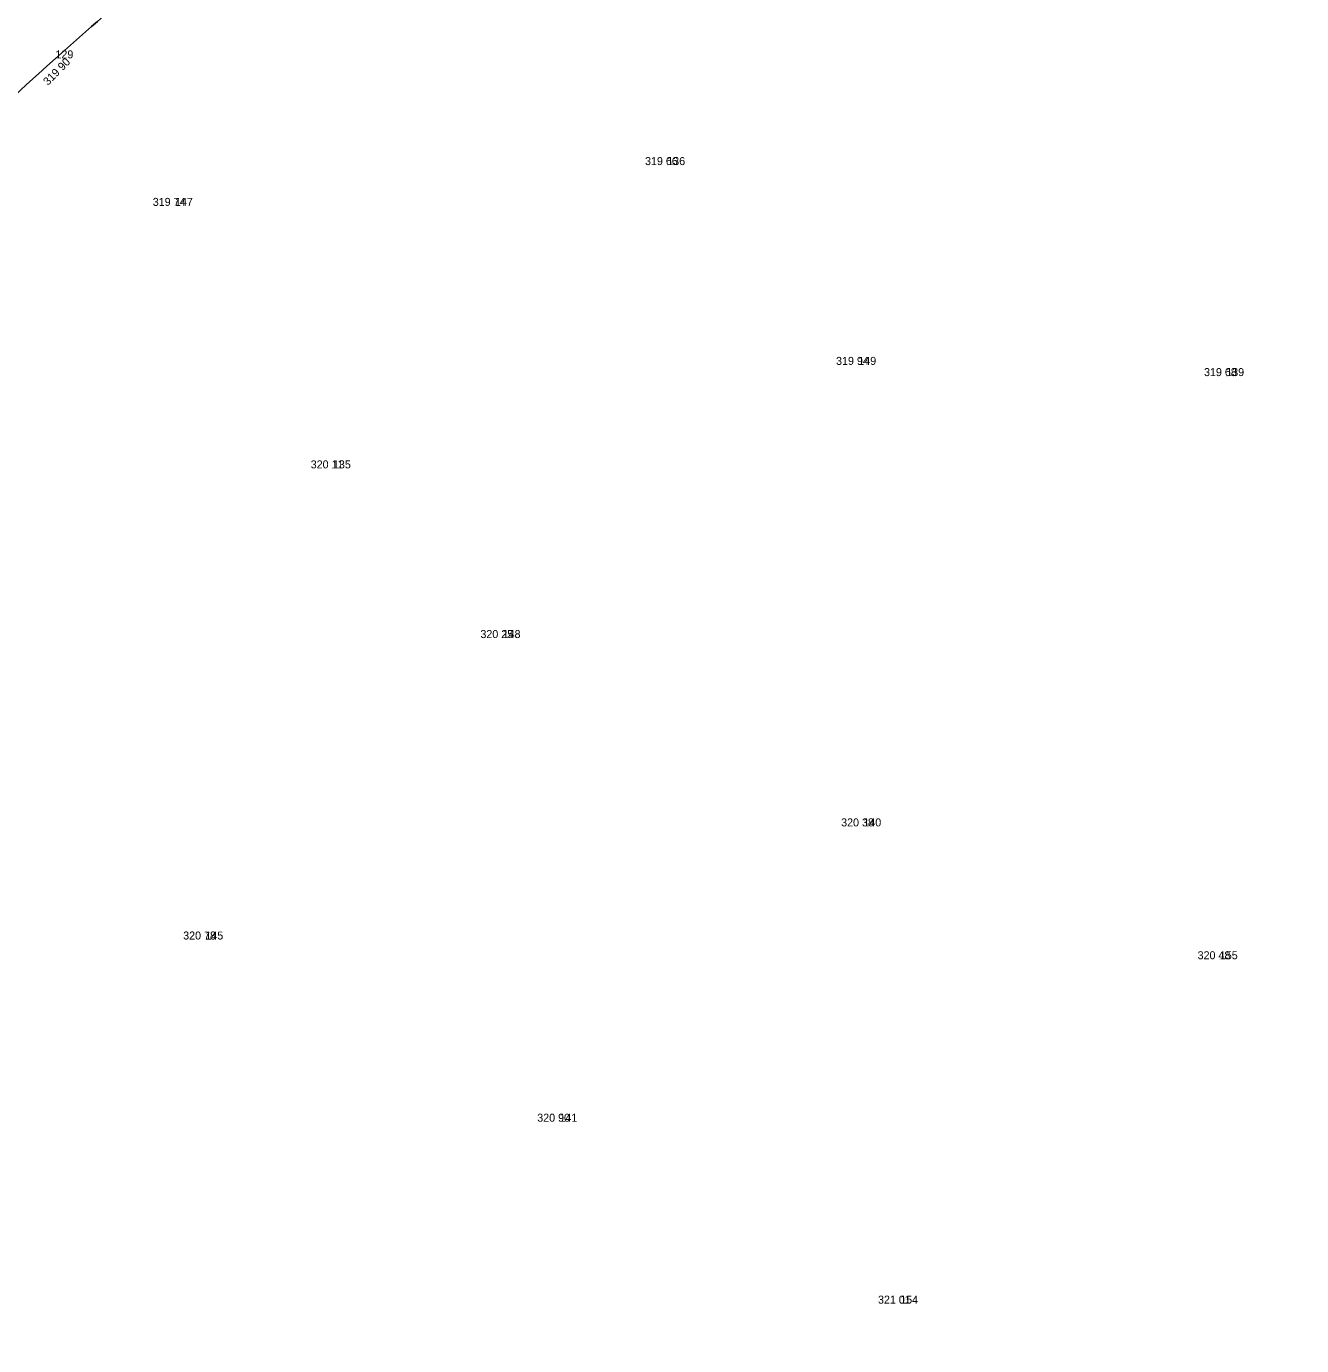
# Model space of a CAD drawing. Extents: x -742884 to -742543, y -1054677 to -1054433.
# Drawn here: x -742753.9 to -742706.11, y -1054570.07 to -1054520.62 of the extents above; entities that cross this region are included whole.
import ezdxf

# ---------------------------------------------------------------- set-up
doc = ezdxf.new("R2010")
doc.units = 0
for name, color, linetype in [('Vrstva 1', 7, 'Continuous'), ('Vrstva 11', 7, 'Continuous'), ('Vrstva 2', 7, 'Continuous'), ('Vrstva 3', 7, 'Continuous'), ('Vrstva 4', 7, 'Continuous')]:
    doc.layers.add(name, color=color, linetype=linetype)

msp = doc.modelspace()

# ---------------------------------------------------------------- linework, layer by layer
at = {"layer": 'Vrstva 1'}
for p, q in [((-742752.81, -1054521.82), (-742752.81, -1054521.82)), ((-742729.88, -1054525.82), (-742729.88, -1054525.82)), ((-742748.33, -1054527.35), (-742748.33, -1054527.35)), ((-742722.72, -1054533.31), (-742722.72, -1054533.31)), ((-742708.93, -1054533.73), (-742708.93, -1054533.73)), ((-742742.41, -1054537.19), (-742742.41, -1054537.19)), ((-742736.05, -1054543.55), (-742736.05, -1054543.55)), ((-742722.53, -1054550.61), (-742722.53, -1054550.61)), ((-742747.19, -1054554.85), (-742747.19, -1054554.85)), ((-742709.17, -1054555.59), (-742709.17, -1054555.59)), ((-742733.92, -1054561.68), (-742733.92, -1054561.68)), ((-742721.15, -1054568.5), (-742721.15, -1054568.5))]:
    msp.add_line(p, q, dxfattribs=at)
at = {"layer": 'Vrstva 11'}
for points in [[(-742777.63, -1054542.12), (-742764.61, -1054526.83), (-742751.7, -1054511.56), (-742738.47, -1054495.82), (-742727.02, -1054482.18), (-742726.38, -1054482.19), (-742725.15, -1054482.94)], [(-742776.7, -1054542.68), (-742764.01, -1054527.79), (-742751.11, -1054512.75), (-742737.61, -1054496.47), (-742726.42, -1054483.98), (-742725.9, -1054484.03), (-742714, -1054491.86), (-742704.819, -1054497.481), (-742700.94, -1054500.269), (-742696.44, -1054503.39), (-742688.83, -1054509.5), (-742682.54, -1054514.17), (-742675.15, -1054519.77), (-742673.01, -1054522.11), (-742671.05, -1054524.7)], [(-742641.45, -1054542), (-742646.08, -1054542.32), (-742650.28, -1054545.1), (-742653.63, -1054549.14), (-742658.66, -1054557.13), (-742664.13, -1054565.84), (-742667.81, -1054569.62), (-742669.76, -1054570.07), (-742674.4, -1054567.88), (-742684.66, -1054562.03), (-742693.02, -1054556.88), (-742694.43, -1054554.37), (-742693.99, -1054552.67), (-742684.52, -1054539.64), (-742677.51, -1054529.95), (-742676.26, -1054526.54), (-742677.27, -1054522.39), (-742681.19, -1054517.29), (-742689.28, -1054510.73), (-742697.86, -1054505.14), (-742704.02, -1054502.75), (-742713.11, -1054501.07), (-742723.98, -1054503.51), (-742736.77, -1054510.1), (-742745.39, -1054515.75), (-742752.81, -1054521.82), (-742762.72, -1054531.38), (-742770.54, -1054539.36), (-742775.54, -1054544.64)]]:
    msp.add_spline(points, degree=3, dxfattribs=at)
at = {"layer": 'Vrstva 4'}
for points in [[(-742783.23, -1054536.93), (-742770.7, -1054522.44), (-742757.28, -1054506.67), (-742744.15, -1054491.3), (-742731.95, -1054477.03), (-742724.73, -1054468.59)], [(-742718.8, -1054478.84), (-742709.4, -1054484.88), (-742695.99, -1054493.43), (-742680.4, -1054503.55), (-742661.01, -1054516), (-742635.78, -1054532.31)], [(-742778.49, -1054541.37), (-742765.63, -1054526.43), (-742752.39, -1054510.77), (-742739.19, -1054495.37), (-742727.3, -1054481.14)]]:
    msp.add_spline(points, degree=3, dxfattribs=at)

# ---------------------------------------------------------------- texts
at = {"layer": 'Vrstva 2'}
for s, p in [('129', (-742752.81, -1054521.82)), ('136', (-742729.88, -1054525.82)), ('147', (-742748.33, -1054527.35)), ('149', (-742722.72, -1054533.31)), ('139', (-742708.93, -1054533.73)), ('135', (-742742.41, -1054537.19)), ('148', (-742736.05, -1054543.55)), ('140', (-742722.53, -1054550.61)), ('145', (-742747.19, -1054554.85)), ('155', (-742709.17, -1054555.59)), ('141', (-742733.92, -1054561.68)), ('154', (-742721.15, -1054568.5))]:
    msp.add_text(s, height=0.3, dxfattribs=at).set_placement(p)
at = {"layer": 'Vrstva 3'}
msp.add_text('319 90 ', height=0.3, rotation=45.4755, dxfattribs=at).set_placement((-742753.091, -1054522.854))
for s, p in [('319 66 ', (-742730.713, -1054525.82)), ('319 74 ', (-742749.163, -1054527.35)), ('319 94 ', (-742723.553, -1054533.31)), ('319 68 ', (-742709.763, -1054533.73)), ('320 11 ', (-742743.243, -1054537.19)), ('320 25 ', (-742736.883, -1054543.55)), ('320 38 ', (-742723.363, -1054550.61)), ('320 78 ', (-742748.023, -1054554.85)), ('320 48 ', (-742710.003, -1054555.59)), ('320 90 ', (-742734.753, -1054561.68)), ('321 01 ', (-742721.983, -1054568.5))]:
    msp.add_text(s, height=0.3, dxfattribs=at).set_placement(p)

doc.saveas('drawing.dxf')
